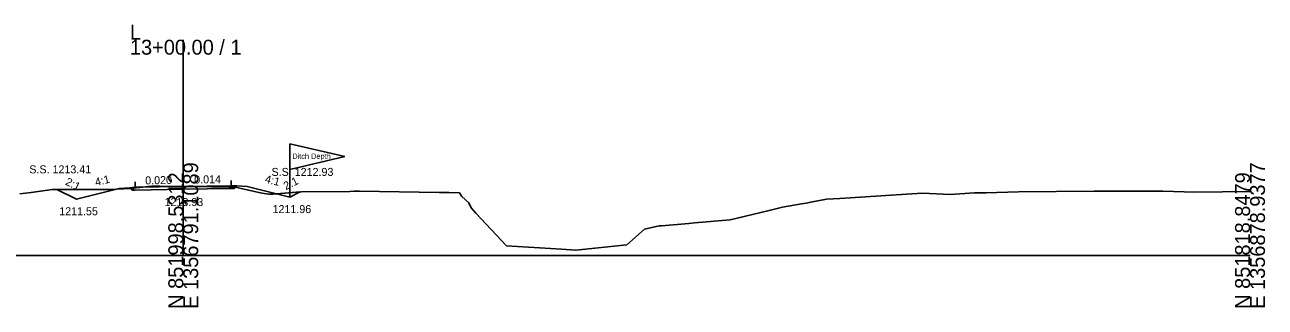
# Model space of a CAD drawing. Extents: x -26 to 3203, y -10 to 4066.
# Drawn here: x 170.3 to 402.8, y 2490.3 to 2543.3 of the extents above; entities that cross this region are included whole.
import ezdxf

# ---------------------------------------------------------------- set-up
doc = ezdxf.new("R2010")
doc.units = 0
for name, color, linetype in [('Exist Cross Section Cell', 7, 'Continuous'), ('Exist XS Center Line Elevation Label', 7, 'Continuous'), ('Exist XS Ground Line', 7, 'Continuous'), ('Prop XS Ditch Slope Text', 7, 'Continuous'), ('Prop XS Ditch Standard Text', 7, 'Continuous'), ('Prop XS Dump Level', 7, 'Continuous'), ('Prop XS Earthwork Shape', 7, 'Continuous'), ('Prop XS EOT Tick Mark', 7, 'Continuous'), ('Prop XS Finish Grade', 7, 'Continuous'), ('Prop XS Finish Grade Earthwork', 7, 'Continuous'), ('Prop XS Finish Grade Pavement', 7, 'Continuous'), ('Prop XS Pvmt Edge Slope', 7, 'Continuous'), ('Prop XS SE Text', 7, 'Continuous'), ('Prop XS Side Slope Text', 7, 'Continuous'), ('Prop XS SS Elevation Text', 7, 'Continuous'), ('Prop XS Subgrade Earthwork', 7, 'Continuous')]:
    doc.layers.add(name, color=color, linetype=linetype)

msp = doc.modelspace()

# ---------------------------------------------------------------- linework, layer by layer
at = {"layer": 'Exist Cross Section Cell'}
for p, q in [((200, 2500), (200, 2540.47)), ((0, 2500), (200, 2500)), ((200, 2500), (400, 2500))]:
    msp.add_line(p, q, dxfattribs=at)
at = {"layer": 'Exist XS Ground Line'}
for p, q in [((169.36, 2511.6), (171.49, 2511.83)), ((171.49, 2511.83), (175.45, 2512.41)), ((175.45, 2512.41), (182.94, 2512.38)), ((182.94, 2512.38), (186.46, 2512.36)), ((186.46, 2512.36), (190.57, 2512.63)), ((190.57, 2512.63), (191.89, 2512.73)), ((191.89, 2512.73), (194.02, 2512.98)), ((194.02, 2512.98), (194.54, 2513.01)), ((194.54, 2513.01), (195.64, 2512.99)), ((195.64, 2512.99), (200, 2512.93)), ((200, 2512.93), (205.27, 2512.86)), ((205.27, 2512.86), (207.05, 2512.86)), ((207.05, 2512.86), (210.03, 2512.78)), ((210.03, 2512.78), (214.76, 2511.72)), ((214.76, 2511.72), (216.05, 2511.48)), ((216.05, 2511.48), (216.81, 2511.53)), ((216.81, 2511.53), (222.14, 2511.95)), ((222.14, 2511.95), (231.26, 2512.03)), ((231.26, 2512.03), (232, 2512.04)), ((232, 2512.04), (233.02, 2512.05)), ((233.02, 2512.05), (247.99, 2511.84)), ((247.99, 2511.84), (249.79, 2511.79)), ((249.79, 2511.79), (251.76, 2511.74)), ((251.76, 2511.74), (252.24, 2511.04)), ((323.11, 2510.71), (335.61, 2511.51)), ((335.61, 2511.51), (338.6, 2511.72)), ((338.6, 2511.72), (343.8, 2511.43)), ((343.8, 2511.43), (348.36, 2511.74)), ((348.36, 2511.74), (350.54, 2511.75)), ((350.54, 2511.75), (356.61, 2511.94)), ((356.61, 2511.94), (370.75, 2512.07)), ((370.75, 2512.07), (371.53, 2512.08)), ((371.53, 2512.08), (372.46, 2512.08)), ((372.46, 2512.08), (383.65, 2512.06)), ((383.65, 2512.06), (389.66, 2511.9)), ((389.66, 2511.9), (400, 2512)), ((252.24, 2511.04), (253.57, 2509.87)), ((253.57, 2509.87), (254, 2508.92)), ((312.35, 2509.08), (315.93, 2509.7)), ((315.93, 2509.7), (316.76, 2509.83)), ((316.76, 2509.83), (317.66, 2510.03)), ((317.66, 2510.03), (320.58, 2510.56)), ((320.58, 2510.56), (323.11, 2510.71)), ((254, 2508.92), (254.88, 2507.97)), ((254.88, 2507.97), (260.62, 2501.83)), ((302.51, 2506.71), (305.15, 2507.29)), ((305.15, 2507.29), (309.83, 2508.47)), ((309.83, 2508.47), (312.35, 2509.08)), ((283.17, 2502.03), (286.5, 2504.92)), ((286.5, 2504.92), (289.2, 2505.55)), ((289.2, 2505.55), (289.69, 2505.57)), ((289.69, 2505.57), (294.76, 2506.03)), ((294.76, 2506.03), (295.84, 2506.14)), ((295.84, 2506.14), (302.51, 2506.71)), ((260.62, 2501.83), (270.92, 2501.18)), ((270.92, 2501.18), (273.6, 2501.03)), ((273.6, 2501.03), (283.17, 2502.03))]:
    msp.add_line(p, q, dxfattribs=at)
at = {"layer": 'Prop XS Dump Level'}
for p, q in [((220, 2516.16), (220, 2520.96)), ((220, 2520.96), (230.3, 2518.56)), ((230.3, 2518.56), (220, 2516.16)), ((220, 2510.96), (220, 2516.16)), ((191, 2512.79), (200, 2512.97)), ((200, 2512.97), (209, 2513.1))]:
    msp.add_line(p, q, dxfattribs=at)
at = {"layer": 'Prop XS Earthwork Shape'}
for points in [[(180, 2510.55), (176.28, 2512.41), (182.94, 2512.38), (186.46, 2512.36), (187.51, 2512.43)], [(189.98, 2512.71), (188, 2512.55), (187.51, 2512.43), (190.09, 2512.59)], [(190.45, 2512.24), (190.09, 2512.59), (190.57, 2512.63), (191.89, 2512.73), (194.02, 2512.98), (194.54, 2513.01), (195.64, 2512.99), (200, 2512.93), (205.27, 2512.86), (207.05, 2512.86), (209.76, 2512.79), (209.53, 2512.57), (209, 2512.56), (200, 2512.43), (191, 2512.25)], [(210.03, 2512.78), (214.76, 2511.72), (216.05, 2511.48), (216.81, 2511.53), (217.51, 2511.59), (212, 2512.96), (210.02, 2513.05), (209.76, 2512.79)], [(220, 2510.96), (221.94, 2511.93), (217.51, 2511.59)]]:
    msp.add_lwpolyline(points, close=True, dxfattribs=at)
at = {"layer": 'Prop XS EOT Tick Mark'}
for p, q in [((209, 2513.1), (209, 2514.1)), ((191, 2512.79), (191, 2513.79))]:
    msp.add_line(p, q, dxfattribs=at)
at = {"layer": 'Prop XS Finish Grade'}
for p, q in [((191, 2512.79), (189.98, 2512.71)), ((209, 2513.1), (210.02, 2513.05))]:
    msp.add_line(p, q, dxfattribs=at)
at = {"layer": 'Prop XS Finish Grade Earthwork'}
for p, q in [((180, 2510.55), (176.28, 2512.41)), ((188, 2512.55), (180, 2510.55)), ((189.98, 2512.71), (188, 2512.55)), ((210.02, 2513.05), (212, 2512.96)), ((212, 2512.96), (220, 2510.96)), ((220, 2510.96), (221.94, 2511.93))]:
    msp.add_line(p, q, dxfattribs=at)
at = {"layer": 'Prop XS Finish Grade Pavement'}
for p, q in [((191, 2512.79), (200, 2512.97)), ((200, 2512.97), (209, 2513.1))]:
    msp.add_line(p, q, dxfattribs=at)
at = {"layer": 'Prop XS Pvmt Edge Slope'}
for p, q in [((191, 2512.79), (190.45, 2512.24)), ((209, 2513.1), (209.53, 2512.57))]:
    msp.add_line(p, q, dxfattribs=at)
at = {"layer": 'Prop XS Subgrade Earthwork'}
for p, q in [((190.45, 2512.24), (189.98, 2512.71)), ((191, 2512.25), (190.45, 2512.24)), ((200, 2512.43), (191, 2512.25)), ((209, 2512.56), (200, 2512.43)), ((209, 2512.56), (209.53, 2512.57)), ((209.53, 2512.57), (210.02, 2513.05))]:
    msp.add_line(p, q, dxfattribs=at)

# ---------------------------------------------------------------- texts
at = {"layer": 'Exist Cross Section Cell'}
for s, p in [('L', (190, 2540.47)), ('13+00.00 / 1', (190, 2537.67))]:
    msp.add_text(s, height=2.8, dxfattribs=at).set_placement(p)
for s, p in [('E 1356791.1089', (202.8, 2490)), ('E 1356878.9377', (402.8, 2490)), ('N 851998.5312', (200, 2490)), ('N 851818.8479', (400, 2490))]:
    msp.add_text(s, height=2.8, rotation=90, dxfattribs=at).set_placement(p)
at = {"layer": 'Exist XS Center Line Elevation Label'}
msp.add_text('1213.93', height=1.5, dxfattribs=at).set_placement((196.49, 2509.28))
at = {"layer": 'Prop XS Ditch Slope Text'}
for rotation, p in [(14.0362, (183.64, 2513)), (345.9638, (215.21, 2513.71))]:
    msp.add_text('4:1', height=1.5, rotation=rotation, dxfattribs=at).set_placement(p)
at = {"layer": 'Prop XS Ditch Standard Text'}
for s, p in [('1211.96', (216.74, 2507.96)), ('1211.55', (176.75, 2507.55))]:
    msp.add_text(s, height=1.5, dxfattribs=at).set_placement(p)
at = {"layer": 'Prop XS Dump Level'}
for s, height, p in [('Ditch Depth', 1, (220.44, 2518.13)), ('Case1', 0.04, (188, 2512.51)), ('Case1', 0.04, (212, 2512.92))]:
    msp.add_text(s, height=height, dxfattribs=at).set_placement(p)
at = {"layer": 'Prop XS SE Text'}
for s, rotation, p in [('0.020', 1.1458, (192.88, 2513.33)), ('0.014', 0.8275, (202.06, 2513.5))]:
    msp.add_text(s, height=1.5, rotation=rotation, dxfattribs=at).set_placement(p)
at = {"layer": 'Prop XS Side Slope Text'}
for rotation, p in [(333.4349, (177.75, 2513.35)), (26.5651, (219.24, 2512.26))]:
    msp.add_text('2:1', height=1.5, rotation=rotation, dxfattribs=at).set_placement(p)
at = {"layer": 'Prop XS SS Elevation Text'}
for s, p in [('S.S. 1213.41', (171.14, 2515.41)), ('S.S. 1212.93', (216.55, 2514.93))]:
    msp.add_text(s, height=1.5, dxfattribs=at).set_placement(p)

doc.saveas('drawing.dxf')
